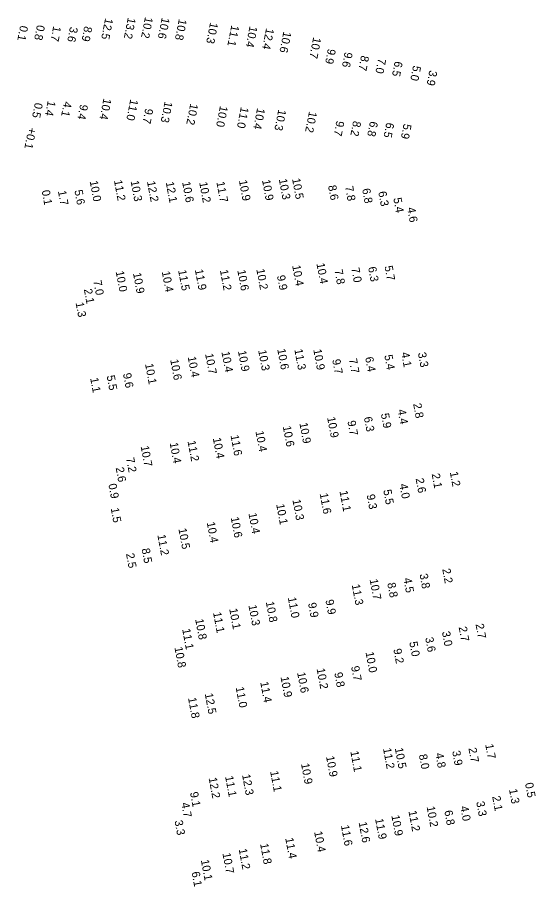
# Model space of a CAD drawing. Extents: x 815385 to 820851, y 582449 to 604245.
# Drawn here: x 816354 to 816671, y 598376 to 598908 of the extents above; entities that cross this region are included whole.
import ezdxf

# ---------------------------------------------------------------- set-up
doc = ezdxf.new("R2010")
doc.units = 0
doc.layers.add('V-TOPO-SOUN-021909', color=7, linetype='Continuous')

msp = doc.modelspace()

# ---------------------------------------------------------------- texts
at = {"layer": 'V-TOPO-SOUN-021909'}
for s, rotation, p in [('12.5 ', 258.865, (816407.54, 598907.72)), ('13.2 ', 258.865, (816421.42, 598908.05)), ('10.2 ', 258.865, (816431.94, 598908.45)), ('10.6 ', 258.865, (816442.18, 598908.09)), ('10.8 ', 258.865, (816452.67, 598907.23)), ('0.1', 258.865, (816355.48, 598903.22)), ('0.8', 258.865, (816365.81, 598903.59)), ('1.7', 258.865, (816375.79, 598902.9)), ('3.6', 258.865, (816386.02, 598902.47)), ('8.9', 258.865, (816394.78, 598902.81)), ('10.3 ', 258.865, (816471.79, 598905.15)), ('11.1 ', 258.865, (816484.79, 598903.45)), ('10.4 ', 258.865, (816495.94, 598902.83)), ('12.4 ', 258.865, (816506.06, 598901.58)), ('10.6 ', 258.865, (816516.65, 598899.58)), ('10.7 ', 258.865, (816534.91, 598896.03)), ('9.9', 258.865, (816543.86, 598889.03)), ('9.6', 258.865, (816554.17, 598887.02)), ('8.7', 258.865, (816564.24, 598884.92)), ('7.0', 258.865, (816574.66, 598883.18)), ('6.5', 258.865, (816584.82, 598881.42)), ('5.0', 258.865, (816596.05, 598878.76)), ('3.9', 258.865, (816605.99, 598875.8)), ('10.4 ', 258.865, (816406.52, 598858.65)), ('11.0 ', 258.865, (816422.94, 598858.1)), ('0.5', 258.865, (816364.51, 598856.04)), ('1.4', 258.865, (816372.38, 598857.25)), ('4.1', 258.865, (816382.28, 598856.79)), ('9.4', 258.865, (816392.24, 598855.03)), ('9.7', 258.865, (816432.1, 598852.55)), ('10.3 ', 258.865, (816443.96, 598856.8)), ('10.2 ', 258.865, (816459.64, 598855.46)), ('10.0 ', 258.865, (816477.85, 598854.11)), ('11.0 ', 258.865, (816490.6, 598853.38)), ('10.4 ', 258.865, (816500.59, 598852.74)), ('10.3 ', 258.865, (816513.56, 598851.91)), ('10.2 ', 258.865, (816532.35, 598850.69)), ('9.7', 258.865, (816549.08, 598844.98)), ('8.2', 258.865, (816559.36, 598844.89)), ('6.8', 258.865, (816569.67, 598844.66)), ('6.5', 258.865, (816579.65, 598843.92)), ('5.9', 258.865, (816590.24, 598843.19)), ('+0.1 ', 258.865, (816360.53, 598840.83)), ('10.5 ', 280.549, (816521.87, 598809.15)), ('10.0 ', 280.549, (816397.98, 598807.71)), ('11.2 ', 280.549, (816412.84, 598808.13)), ('10.3 ', 280.549, (816423.05, 598807.77)), ('12.2 ', 280.549, (816433.06, 598807.46)), ('12.1 ', 280.549, (816444.54, 598807.06)), ('10.6 ', 280.549, (816454.6, 598807.12)), ('10.2 ', 280.549, (816465.03, 598806.93)), ('11.7 ', 280.549, (816475.57, 598807.15)), ('10.9 ', 280.549, (816489.34, 598808.11)), ('10.9 ', 280.549, (816503.48, 598808.34)), ('10.3 ', 280.549, (816513.77, 598808.88)), ('8.6', 280.549, (816543.91, 598804.89)), ('7.8', 280.549, (816554.29, 598804.38)), ('0.1', 280.549, (816368.6, 598801.88)), ('1.7', 280.549, (816378.54, 598801.67)), ('5.6', 280.549, (816388.65, 598802.04)), ('6.8', 280.549, (816564.75, 598802.9)), ('6.3', 280.549, (816574.63, 598801.16)), ('5.4', 280.549, (816583.87, 598797.24)), ('4.6', 280.549, (816592.3, 598791.35)), ('10.4 ', 280.549, (816521.95, 598756.04)), ('10.4 ', 280.549, (816536.79, 598757.33)), ('10.0 ', 280.549, (816413.9, 598752.48)), ('10.9 ', 280.549, (816424.5, 598751.42)), ('10.4 ', 280.549, (816442.13, 598752.32)), ('11.5 ', 280.549, (816452.13, 598753.16)), ('11.9 ', 280.549, (816462.39, 598753.51)), ('11.2 ', 280.549, (816477.7, 598753.28)), ('10.6 ', 280.549, (816488.36, 598753.16)), ('10.2 ', 280.549, (816500, 598753.77)), ('7.8', 280.549, (816547.81, 598753.34)), ('7.0', 280.549, (816558.11, 598754.51)), ('6.3', 280.549, (816568.41, 598755.01)), ('5.7', 280.549, (816578.46, 598755.65)), ('7.0', 280.549, (816400.22, 598746.75)), ('9.9', 280.549, (816512.6, 598749.83)), ('2.1', 280.549, (816394.43, 598741.55)), ('1.3', 280.549, (816389.36, 598733.34)), ('10.4 ', 280.549, (816478.64, 598703.25)), ('10.9 ', 280.549, (816488.75, 598703.77)), ('10.3 ', 280.549, (816501.13, 598704.21)), ('10.6 ', 280.549, (816512.82, 598704.87)), ('11.3 ', 280.549, (816523.28, 598704.75)), ('10.9 ', 280.549, (816534.87, 598704.63)), ('3.3', 280.549, (816598.91, 598702.64)), ('10.6 ', 280.549, (816447.29, 598698.45)), ('10.4 ', 280.549, (816458, 598700.17)), ('10.7 ', 280.549, (816468.64, 598702.01)), ('9.7', 280.549, (816546.44, 598698.49)), ('7.7', 280.549, (816556.62, 598698.89)), ('6.4', 280.549, (816566.58, 598699.88)), ('5.4', 280.549, (816578.33, 598701.17)), ('4.1', 280.549, (816588.65, 598702.71)), ('10.1 ', 280.549, (816431.88, 598695.86)), ('1.1', 280.549, (816398.3, 598687.2)), ('5.5', 280.549, (816408.37, 598688.6)), ('9.6', 280.549, (816418.37, 598689.97)), ('2.8', 280.549, (816595.99, 598671.52)), ('5.9', 280.549, (816576.23, 598665.36)), ('4.4', 280.549, (816586.43, 598667.78)), ('10.9 ', 280.549, (816543.32, 598663.19)), ('9.7', 280.549, (816555.77, 598660.87)), ('6.3', 280.549, (816565.81, 598663.22)), ('10.6 ', 280.549, (816516.21, 598657.68)), ('10.9 ', 280.549, (816526.36, 598659.67)), ('10.4 ', 280.549, (816473.38, 598650.47)), ('11.6 ', 280.549, (816484.22, 598652.16)), ('10.4 ', 280.549, (816499.47, 598654.65)), ('10.7 ', 280.549, (816429.2, 598645.52)), ('10.4 ', 280.549, (816446.95, 598647.54)), ('11.2 ', 280.549, (816457.88, 598648.67)), ('7.2', 280.549, (816420.24, 598638.32)), ('2.6', 280.549, (816413.9, 598632.42)), ('2.1', 280.549, (816607.33, 598628.59)), ('1.2', 280.549, (816618.46, 598629.69)), ('2.6', 280.549, (816597.5, 598625.72)), ('0.9', 280.549, (816409.43, 598622.3)), ('11.1 ', 280.549, (816550.92, 598618.05)), ('5.5', 280.549, (816577.7, 598618.71)), ('4.0', 280.549, (816587.57, 598622.28)), ('10.3 ', 280.549, (816522.1, 598612.73)), ('11.6 ', 280.549, (816538.78, 598616.57)), ('9.3', 280.549, (816567.5, 598615.79)), ('1.5', 280.549, (816410.87, 598607.6)), ('10.1 ', 280.549, (816512.16, 598609.99)), ('10.6 ', 280.549, (816484.32, 598602)), ('10.4 ', 280.549, (816495.19, 598604.48)), ('10.4 ', 280.549, (816469.65, 598598.93)), ('11.2 ', 280.549, (816439.42, 598591.25)), ('10.5 ', 280.549, (816452.3, 598595.05)), ('8.5', 280.549, (816429.78, 598582.75)), ('2.5', 280.549, (816420.22, 598579.78)), ('2.2', 280.549, (816613.8, 598570.44)), ('4.5', 280.549, (816590.04, 598564.7)), ('3.8', 280.549, (816599.9, 598567.21)), ('11.3 ', 280.549, (816558.41, 598560.8)), ('10.7 ', 280.549, (816569.35, 598564.03)), ('8.8', 280.549, (816580.19, 598561.75)), ('10.8 ', 280.549, (816505.8, 598550.29)), ('11.0 ', 280.549, (816519.29, 598552.93)), ('9.9', 280.549, (816531.66, 598549.49)), ('9.9', 280.549, (816542.31, 598551.38)), ('11.1 ', 280.549, (816473.51, 598543.79)), ('10.1 ', 280.549, (816483.41, 598546.03)), ('10.3 ', 280.549, (816495.18, 598548.22)), ('10.8 ', 280.549, (816462.58, 598539.67)), ('11.1 ', 280.549, (816454.61, 598533.62)), ('2.7', 280.549, (816623.87, 598534.88)), ('2.7', 280.549, (816634.19, 598536.64)), ('3.6', 280.549, (816603.36, 598528.41)), ('3.0', 280.549, (816613.6, 598532)), ('10.8 ', 280.549, (816449.87, 598522.49)), ('5.0', 280.549, (816593.64, 598525.7)), ('10.0 ', 280.549, (816566.86, 598519.49)), ('9.2', 280.549, (816583.89, 598521.36)), ('10.6 ', 280.549, (816524.98, 598507.05)), ('10.2 ', 280.549, (816536.9, 598509.44)), ('9.8', 280.549, (816547.71, 598506.89)), ('9.7', 280.549, (816558.01, 598510.74)), ('11.4 ', 280.549, (816502.39, 598501.23)), ('10.9 ', 280.549, (816514.82, 598504.39)), ('11.0 ', 280.549, (816487.35, 598498.05)), ('11.8 ', 280.549, (816458.19, 598491.54)), ('12.5 ', 280.549, (816468.44, 598494.14)), ('11.1 ', 280.549, (816557.54, 598458.85)), ('11.2 ', 280.549, (816577.54, 598460.64)), ('10.5 ', 280.549, (816584.78, 598460.79)), ('3.9', 280.549, (816619.86, 598458.98)), ('2.7', 280.549, (816629.83, 598460.79)), ('1.7', 280.549, (816640.12, 598463.07)), ('10.9 ', 280.549, (816542.67, 598455.74)), ('8.0', 280.549, (816599.49, 598456.81)), ('4.8', 280.549, (816609.54, 598457.55)), ('10.9 ', 280.549, (816527.36, 598451.26)), ('12.2 ', 280.549, (816470.8, 598442.6)), ('11.1 ', 280.549, (816480.88, 598443.54)), ('12.3 ', 280.549, (816491.26, 598444.55)), ('11.1 ', 280.549, (816508.45, 598446.63)), ('0.5', 280.549, (816664.48, 598439.37)), ('9.1', 280.549, (816459.39, 598433.73)), ('1.3', 280.549, (816654.68, 598435.64)), ('4.7', 280.549, (816454.01, 598427.22)), ('3.3', 280.549, (816634.6, 598427.96)), ('2.1', 280.549, (816644.38, 598431.28)), ('11.2 ', 280.549, (816593.13, 598422.3)), ('10.2 ', 280.549, (816604.24, 598425.01)), ('6.8', 280.549, (816615.07, 598422.48)), ('4.0', 280.549, (816624.79, 598425.08)), ('3.3', 280.549, (816449.92, 598416.42)), ('11.9 ', 280.549, (816572.72, 598417.53)), ('10.9 ', 280.549, (816582.66, 598419.6)), ('11.6 ', 280.549, (816551.78, 598413.5)), ('12.6 ', 280.549, (816562.61, 598415.46)), ('11.4 ', 280.549, (816517.7, 598405.73)), ('10.4 ', 280.549, (816535.38, 598409.67)), ('11.8 ', 280.549, (816502.31, 598402.27)), ('10.7 ', 280.549, (816479.25, 598396.51)), ('11.2 ', 280.549, (816489.2, 598399.08)), ('10.1 ', 280.549, (816466.04, 598392.36)), ('6.1', 280.549, (816460.35, 598384.99))]:
    msp.add_text(s, height=5, rotation=rotation, dxfattribs=at).set_placement(p)

doc.saveas('drawing.dxf')
